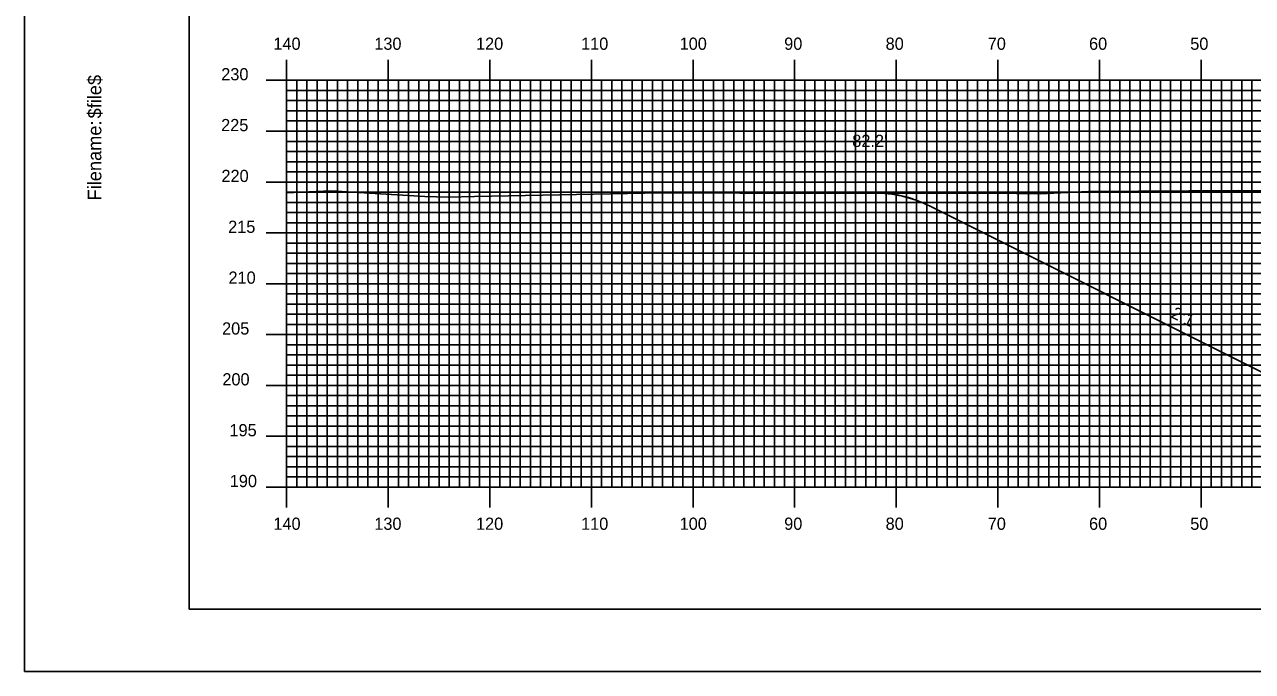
# Model space of a CAD drawing. Extents: x 1800749 to 1801092, y 442591 to 442811.
# Drawn here: x 1800748.8 to 1800869.6, y 442590.5 to 442654.2 of the extents above; entities that cross this region are included whole.
import ezdxf

# ---------------------------------------------------------------- set-up
doc = ezdxf.new("R2010")
doc.units = 0
for name, color, linetype in [('ANNOTATION', 7, 'Continuous'), ('BORDER', 7, 'Continuous'), ('D_Roadway_SlopeLines', 7, 'Continuous'), ('D_Text_Standard', 7, 'Continuous'), ('H_V ANNOTATION', 7, 'Continuous'), ('MAJOR', 7, 'Continuous'), ('MINOR', 7, 'Continuous'), ('PLOT BOUNDARY', 7, 'Continuous'), ('S_Roadway_Centerline', 7, 'Continuous')]:
    doc.layers.add(name, color=color, linetype=linetype)

msp = doc.modelspace()

# ---------------------------------------------------------------- linework, layer by layer
at = {"layer": 'ANNOTATION'}
msp.add_arc((1800832.45, 442625.58), 12, 63.4349, 90.4821, dxfattribs=at)
msp.add_arc((1800832.45, 442625.58), 12, 63.4349, 90.4821, dxfattribs=at)
at = {"layer": 'BORDER'}
msp.add_lwpolyline([(1800764.95, 442596.67), (1801084.95, 442596.67), (1801084.95, 442806.67), (1800764.95, 442806.67)], close=True, dxfattribs=at)
at = {"layer": 'D_Roadway_SlopeLines'}
msp.add_line((1800880.38, 442615.04), (1800837.81, 442636.32), dxfattribs=at)
msp.add_arc((1800832.66, 442626.47), 11.12, 71.5651, 89.3425, dxfattribs=at)
at = {"layer": 'MAJOR'}
for p, q in [((1800774.55, 442650.67), (1800774.55, 442648.67)), ((1800784.55, 442650.67), (1800784.55, 442648.67)), ((1800794.55, 442650.67), (1800794.55, 442648.67)), ((1800804.55, 442650.67), (1800804.55, 442648.67)), ((1800814.55, 442650.67), (1800814.55, 442648.67)), ((1800824.55, 442650.67), (1800824.55, 442648.67)), ((1800834.55, 442650.67), (1800834.55, 442648.67)), ((1800844.55, 442650.67), (1800844.55, 442648.67)), ((1800854.55, 442650.67), (1800854.55, 442648.67)), ((1800864.55, 442650.67), (1800864.55, 442648.67)), ((1800772.55, 442648.67), (1800774.55, 442648.67)), ((1800774.55, 442648.67), (1801054.55, 442648.67)), ((1800774.55, 442608.67), (1800774.55, 442648.67)), ((1800774.55, 442608.67), (1800774.55, 442648.67)), ((1800774.55, 442648.67), (1801054.55, 442648.67)), ((1800784.55, 442608.67), (1800784.55, 442648.67)), ((1800794.55, 442608.67), (1800794.55, 442648.67)), ((1800804.55, 442608.67), (1800804.55, 442648.67)), ((1800814.55, 442608.67), (1800814.55, 442648.67)), ((1800824.55, 442608.67), (1800824.55, 442648.67)), ((1800834.55, 442608.67), (1800834.55, 442648.67)), ((1800844.55, 442608.67), (1800844.55, 442648.67)), ((1800854.55, 442608.67), (1800854.55, 442648.67)), ((1800864.55, 442608.67), (1800864.55, 442648.67)), ((1800772.55, 442643.67), (1800774.55, 442643.67)), ((1800774.55, 442643.67), (1801054.55, 442643.67)), ((1800772.55, 442638.67), (1800774.55, 442638.67)), ((1800774.55, 442638.67), (1801054.55, 442638.67)), ((1800772.55, 442633.67), (1800774.55, 442633.67)), ((1800774.55, 442633.67), (1801054.55, 442633.67)), ((1800772.55, 442628.67), (1800774.55, 442628.67)), ((1800774.55, 442628.67), (1801054.55, 442628.67)), ((1800772.55, 442623.67), (1800774.55, 442623.67)), ((1800774.55, 442623.67), (1801054.55, 442623.67)), ((1800772.55, 442618.67), (1800774.55, 442618.67)), ((1800774.55, 442618.67), (1801054.55, 442618.67)), ((1800772.55, 442613.67), (1800774.55, 442613.67)), ((1800774.55, 442613.67), (1801054.55, 442613.67)), ((1800772.55, 442608.67), (1800774.55, 442608.67)), ((1800774.55, 442608.67), (1801054.55, 442608.67)), ((1800774.55, 442608.67), (1801054.55, 442608.67)), ((1800774.55, 442606.66), (1800774.55, 442608.67)), ((1800784.55, 442606.66), (1800784.55, 442608.67)), ((1800794.55, 442606.66), (1800794.55, 442608.67)), ((1800804.55, 442606.66), (1800804.55, 442608.67)), ((1800814.55, 442606.66), (1800814.55, 442608.67)), ((1800824.55, 442606.66), (1800824.55, 442608.67)), ((1800834.55, 442606.66), (1800834.55, 442608.67)), ((1800844.55, 442606.66), (1800844.55, 442608.67)), ((1800854.55, 442606.66), (1800854.55, 442608.67)), ((1800864.55, 442606.66), (1800864.55, 442608.67))]:
    msp.add_line(p, q, dxfattribs=at)
at = {"layer": 'MINOR'}
for p, q in [((1800775.55, 442608.67), (1800775.55, 442648.67)), ((1800776.55, 442608.67), (1800776.55, 442648.67)), ((1800777.55, 442608.67), (1800777.55, 442648.67)), ((1800778.55, 442608.67), (1800778.55, 442648.67)), ((1800779.55, 442608.67), (1800779.55, 442648.67)), ((1800780.55, 442608.67), (1800780.55, 442648.67)), ((1800781.55, 442608.67), (1800781.55, 442648.67)), ((1800782.55, 442608.67), (1800782.55, 442648.67)), ((1800783.55, 442608.67), (1800783.55, 442648.67)), ((1800785.55, 442608.67), (1800785.55, 442648.67)), ((1800786.55, 442608.67), (1800786.55, 442648.67)), ((1800787.55, 442608.67), (1800787.55, 442648.67)), ((1800788.55, 442608.67), (1800788.55, 442648.67)), ((1800789.55, 442608.67), (1800789.55, 442648.67)), ((1800790.55, 442608.67), (1800790.55, 442648.67)), ((1800791.55, 442608.67), (1800791.55, 442648.67)), ((1800792.55, 442608.67), (1800792.55, 442648.67)), ((1800793.55, 442608.67), (1800793.55, 442648.67)), ((1800795.55, 442608.67), (1800795.55, 442648.67)), ((1800796.55, 442608.67), (1800796.55, 442648.67)), ((1800797.55, 442608.67), (1800797.55, 442648.67)), ((1800798.55, 442608.67), (1800798.55, 442648.67)), ((1800799.55, 442608.67), (1800799.55, 442648.67)), ((1800800.55, 442608.67), (1800800.55, 442648.67)), ((1800801.55, 442608.67), (1800801.55, 442648.67)), ((1800802.55, 442608.67), (1800802.55, 442648.67)), ((1800803.55, 442608.67), (1800803.55, 442648.67)), ((1800805.55, 442608.67), (1800805.55, 442648.67)), ((1800806.55, 442608.67), (1800806.55, 442648.67)), ((1800807.55, 442608.67), (1800807.55, 442648.67)), ((1800808.55, 442608.67), (1800808.55, 442648.67)), ((1800809.55, 442608.67), (1800809.55, 442648.67)), ((1800810.55, 442608.67), (1800810.55, 442648.67)), ((1800811.55, 442608.67), (1800811.55, 442648.67)), ((1800812.55, 442608.67), (1800812.55, 442648.67)), ((1800813.55, 442608.67), (1800813.55, 442648.67)), ((1800815.55, 442608.67), (1800815.55, 442648.67)), ((1800816.55, 442608.67), (1800816.55, 442648.67)), ((1800817.55, 442608.67), (1800817.55, 442648.67)), ((1800818.55, 442608.67), (1800818.55, 442648.67)), ((1800819.55, 442608.67), (1800819.55, 442648.67)), ((1800820.55, 442608.67), (1800820.55, 442648.67)), ((1800821.55, 442608.67), (1800821.55, 442648.67)), ((1800822.55, 442608.67), (1800822.55, 442648.67)), ((1800823.55, 442608.67), (1800823.55, 442648.67)), ((1800825.55, 442608.67), (1800825.55, 442648.67)), ((1800826.55, 442608.67), (1800826.55, 442648.67)), ((1800827.55, 442608.67), (1800827.55, 442648.67)), ((1800828.55, 442608.67), (1800828.55, 442648.67)), ((1800829.55, 442608.67), (1800829.55, 442648.67)), ((1800830.55, 442608.67), (1800830.55, 442648.67)), ((1800831.55, 442608.67), (1800831.55, 442648.67)), ((1800832.55, 442608.67), (1800832.55, 442648.67)), ((1800833.55, 442608.67), (1800833.55, 442648.67)), ((1800835.55, 442608.67), (1800835.55, 442648.67)), ((1800836.55, 442608.67), (1800836.55, 442648.67)), ((1800837.55, 442608.67), (1800837.55, 442648.67)), ((1800838.55, 442608.67), (1800838.55, 442648.67)), ((1800839.55, 442608.67), (1800839.55, 442648.67)), ((1800840.55, 442608.67), (1800840.55, 442648.67)), ((1800841.55, 442608.67), (1800841.55, 442648.67)), ((1800842.55, 442608.67), (1800842.55, 442648.67)), ((1800843.55, 442608.67), (1800843.55, 442648.67)), ((1800845.55, 442608.67), (1800845.55, 442648.67)), ((1800846.55, 442608.67), (1800846.55, 442648.67)), ((1800847.55, 442608.67), (1800847.55, 442648.67)), ((1800848.55, 442608.67), (1800848.55, 442648.67)), ((1800849.55, 442608.67), (1800849.55, 442648.67)), ((1800850.55, 442608.67), (1800850.55, 442648.67)), ((1800851.55, 442608.67), (1800851.55, 442648.67)), ((1800852.55, 442608.67), (1800852.55, 442648.67)), ((1800853.55, 442608.67), (1800853.55, 442648.67)), ((1800855.55, 442608.67), (1800855.55, 442648.67)), ((1800856.55, 442608.67), (1800856.55, 442648.67)), ((1800857.55, 442608.67), (1800857.55, 442648.67)), ((1800858.55, 442608.67), (1800858.55, 442648.67)), ((1800859.55, 442608.67), (1800859.55, 442648.67)), ((1800860.55, 442608.67), (1800860.55, 442648.67)), ((1800861.55, 442608.67), (1800861.55, 442648.67)), ((1800862.55, 442608.67), (1800862.55, 442648.67)), ((1800863.55, 442608.67), (1800863.55, 442648.67)), ((1800865.55, 442608.67), (1800865.55, 442648.67)), ((1800866.55, 442608.67), (1800866.55, 442648.67)), ((1800867.55, 442608.67), (1800867.55, 442648.67)), ((1800868.55, 442608.67), (1800868.55, 442648.67)), ((1800869.55, 442608.67), (1800869.55, 442648.67)), ((1800774.55, 442647.67), (1801054.55, 442647.67)), ((1800774.55, 442647.67), (1800776.55, 442647.67)), ((1800774.55, 442646.67), (1801054.55, 442646.67)), ((1800774.55, 442646.67), (1800776.55, 442646.67)), ((1800774.55, 442645.67), (1801054.55, 442645.67)), ((1800774.55, 442645.67), (1800776.55, 442645.67)), ((1800774.55, 442644.67), (1801054.55, 442644.67)), ((1800774.55, 442644.67), (1800776.55, 442644.67)), ((1800774.55, 442642.67), (1801054.55, 442642.67)), ((1800774.55, 442642.67), (1800776.55, 442642.67)), ((1800774.55, 442641.67), (1801054.55, 442641.67)), ((1800774.55, 442641.67), (1800776.55, 442641.67)), ((1800774.55, 442640.67), (1801054.55, 442640.67)), ((1800774.55, 442640.67), (1800776.55, 442640.67)), ((1800774.55, 442639.67), (1801054.55, 442639.67)), ((1800774.55, 442639.67), (1800776.55, 442639.67)), ((1800774.55, 442637.67), (1801054.55, 442637.67)), ((1800774.55, 442637.67), (1800776.55, 442637.67)), ((1800774.55, 442636.67), (1801054.55, 442636.67)), ((1800774.55, 442636.67), (1800776.55, 442636.67)), ((1800774.55, 442635.67), (1801054.55, 442635.67)), ((1800774.55, 442635.67), (1800776.55, 442635.67)), ((1800774.55, 442634.67), (1801054.55, 442634.67)), ((1800774.55, 442634.67), (1800776.55, 442634.67)), ((1800774.55, 442632.67), (1801054.55, 442632.67)), ((1800774.55, 442632.67), (1800776.55, 442632.67)), ((1800774.55, 442631.67), (1801054.55, 442631.67)), ((1800774.55, 442631.67), (1800776.55, 442631.67)), ((1800774.55, 442630.67), (1801054.55, 442630.67)), ((1800774.55, 442630.67), (1800776.55, 442630.67)), ((1800774.55, 442629.67), (1801054.55, 442629.67)), ((1800774.55, 442629.67), (1800776.55, 442629.67)), ((1800774.55, 442627.67), (1801054.55, 442627.67)), ((1800774.55, 442627.67), (1800776.55, 442627.67)), ((1800774.55, 442626.67), (1801054.55, 442626.67)), ((1800774.55, 442626.67), (1800776.55, 442626.67)), ((1800774.55, 442625.67), (1801054.55, 442625.67)), ((1800774.55, 442625.67), (1800776.55, 442625.67)), ((1800774.55, 442624.67), (1801054.55, 442624.67)), ((1800774.55, 442624.67), (1800776.55, 442624.67)), ((1800774.55, 442622.67), (1801054.55, 442622.67)), ((1800774.55, 442622.67), (1800776.55, 442622.67)), ((1800774.55, 442621.67), (1801054.55, 442621.67)), ((1800774.55, 442621.67), (1800776.55, 442621.67)), ((1800774.55, 442620.67), (1801054.55, 442620.67)), ((1800774.55, 442620.67), (1800776.55, 442620.67)), ((1800774.55, 442619.67), (1801054.55, 442619.67)), ((1800774.55, 442619.67), (1800776.55, 442619.67)), ((1800774.55, 442617.67), (1801054.55, 442617.67)), ((1800774.55, 442617.67), (1800776.55, 442617.67)), ((1800774.55, 442616.67), (1801054.55, 442616.67)), ((1800774.55, 442616.67), (1800776.55, 442616.67)), ((1800774.55, 442615.67), (1801054.55, 442615.67)), ((1800774.55, 442615.67), (1800776.55, 442615.67)), ((1800774.55, 442614.67), (1801054.55, 442614.67)), ((1800774.55, 442614.67), (1800776.55, 442614.67)), ((1800774.55, 442612.67), (1801054.55, 442612.67)), ((1800774.55, 442612.67), (1800776.55, 442612.67)), ((1800774.55, 442611.67), (1801054.55, 442611.67)), ((1800774.55, 442611.67), (1800776.55, 442611.67)), ((1800774.55, 442610.67), (1801054.55, 442610.67)), ((1800774.55, 442610.67), (1800776.55, 442610.67)), ((1800774.55, 442609.67), (1801054.55, 442609.67)), ((1800774.55, 442609.67), (1800776.55, 442609.67))]:
    msp.add_line(p, q, dxfattribs=at)
at = {"layer": 'PLOT BOUNDARY'}
msp.add_lwpolyline([(1800748.76, 442590.55), (1801088.76, 442590.55), (1801088.76, 442810.55), (1800748.76, 442810.55)], close=True, dxfattribs=at)
at = {"layer": 'S_Roadway_Centerline'}
msp.add_lwpolyline([(1800774.55, 442637.62), (1800778.9, 442637.79), (1800788.16, 442637.26), (1800790.44, 442637.18), (1800793.03, 442637.26), (1800809.77, 442637.58), (1800814.01, 442637.62), (1800819.14, 442637.56), (1800832.05, 442637.58), (1800844.01, 442637.57), (1800848.71, 442637.52), (1800853.46, 442637.73), (1800868.26, 442637.83), (1800871.95, 442637.79)], dxfattribs=at)

# ---------------------------------------------------------------- texts
at = {"layer": 'ANNOTATION'}
msp.add_text('2:1', height=1.2, rotation=333.4349, dxfattribs=at).set_placement((1800861.5, 442625.39))
msp.add_text('2:1', height=1.2, rotation=333.4349, dxfattribs=at).set_placement((1800861.5, 442625.39))
at = {"layer": 'BORDER'}
for s, p in [('$file$', (1800756.32, 442644.92)), ('Filename:', (1800756.32, 442636.86))]:
    msp.add_text(s, height=1.339, rotation=90, dxfattribs=at).set_placement(p)
at = {"layer": 'D_Text_Standard'}
msp.add_text("82.2'", height=1.2, dxfattribs=at).set_placement((1800830.22, 442642.12))
at = {"layer": 'H_V ANNOTATION'}
for s, p in [('140', (1800773.25, 442651.67)), ('130', (1800783.18, 442651.67)), ('120', (1800793.19, 442651.67)), ('110', (1800803.53, 442651.67)), ('100', (1800813.23, 442651.67)), ('90', (1800823.52, 442651.67)), ('80', (1800833.5, 442651.67)), ('70', (1800843.55, 442651.67)), ('60', (1800853.52, 442651.67)), ('50', (1800863.48, 442651.67)), ('230', (1800768.12, 442648.67)), ('225', (1800768.11, 442643.67)), ('220', (1800768.14, 442638.67)), ('215', (1800768.8, 442633.67)), ('210', (1800768.83, 442628.67)), ('205', (1800768.2, 442623.67)), ('200', (1800768.23, 442618.67)), ('195', (1800768.93, 442613.67)), ('190', (1800768.96, 442608.67)), ('140', (1800773.25, 442604.47)), ('130', (1800783.18, 442604.47)), ('120', (1800793.19, 442604.47)), ('110', (1800803.53, 442604.47)), ('100', (1800813.23, 442604.47)), ('90', (1800823.52, 442604.47)), ('80', (1800833.5, 442604.47)), ('70', (1800843.55, 442604.47)), ('60', (1800853.52, 442604.47)), ('50', (1800863.48, 442604.47))]:
    msp.add_text(s, height=1.2, dxfattribs=at).set_placement(p)
at = {"layer": 'MAJOR'}
msp.add_text('-', height=0.012, dxfattribs=at).set_placement((1800774.54, 442608.67))

doc.saveas('drawing.dxf')
